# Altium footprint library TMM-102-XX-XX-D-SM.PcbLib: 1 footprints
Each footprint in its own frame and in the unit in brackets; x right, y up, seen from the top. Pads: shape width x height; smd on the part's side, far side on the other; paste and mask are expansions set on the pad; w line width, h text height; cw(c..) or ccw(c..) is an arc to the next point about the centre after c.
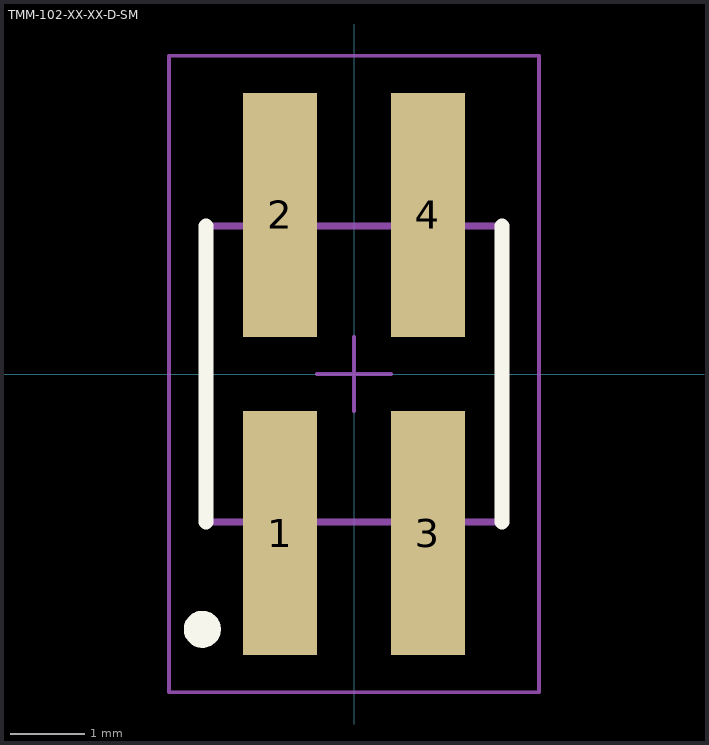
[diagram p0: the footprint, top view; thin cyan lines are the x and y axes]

## TMM-102-XX-XX-D-SM [mm] "2.00mm pitch, 4 pin, terminal strip; double row, SMT"
height 2.77
pads (4):
  rect 1x3.3 smd mask+0: 1(-1,-2.15) 2(-1,2.15) 3(1,-2.15) 4(1,2.15)
Top Overlay:
  circle w0.25: c-2.05,-3.45 r0.125
  lines w0.2: -2,-2 -2,2 ; 2,-2 2,2
Mechanical 12:
  lines w0.001: -2,-2 2,-2 2,2 -2,2 -2,-2
Mechanical 13:
  lines w0.1: -2,-2 2,-2 2,2 -2,2 -2,-2
  text ".Designator" at 0,-0.127 h1.52
Mechanical 15:
  lines w0.05: -0.5,0 0.5,0 ; 0,-0.5 0,0.5 ; -2.5,-4.3 2.5,-4.3 2.5,4.3 -2.5,4.3 -2.5,-4.3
